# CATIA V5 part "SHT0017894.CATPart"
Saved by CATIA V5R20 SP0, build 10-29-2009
Part number: SHT0017894
Bounding box of the stored display mesh (mm): x -453 to 31, y 582 to 876, z 0.9 to 38.4
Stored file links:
  F:\福田A6\17-新能源车\数据\变更后数据\A668100000147（SHT0017898）-副司机座椅底支架总成\SHT0017894-副驾底支架上板\SHT0017894.CATPart

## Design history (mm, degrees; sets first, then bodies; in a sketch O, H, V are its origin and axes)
Body1
Body2 (main body)
Body3 "SHT0017894-副驾底支架上板"
  Solid1: solid without history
